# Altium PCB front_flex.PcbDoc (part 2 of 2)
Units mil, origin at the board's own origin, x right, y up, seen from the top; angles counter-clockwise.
Board outline 5591.04 x 1020.3 mil, 4 copper layers (Layer 1 (Top Layer), Layer 2 (PWR), Layer 3 (GND), Layer 4 (Bottom Layer)), stack 21.036 mil thick; 26 components, 44 nets, 150 pads, 87 vias.
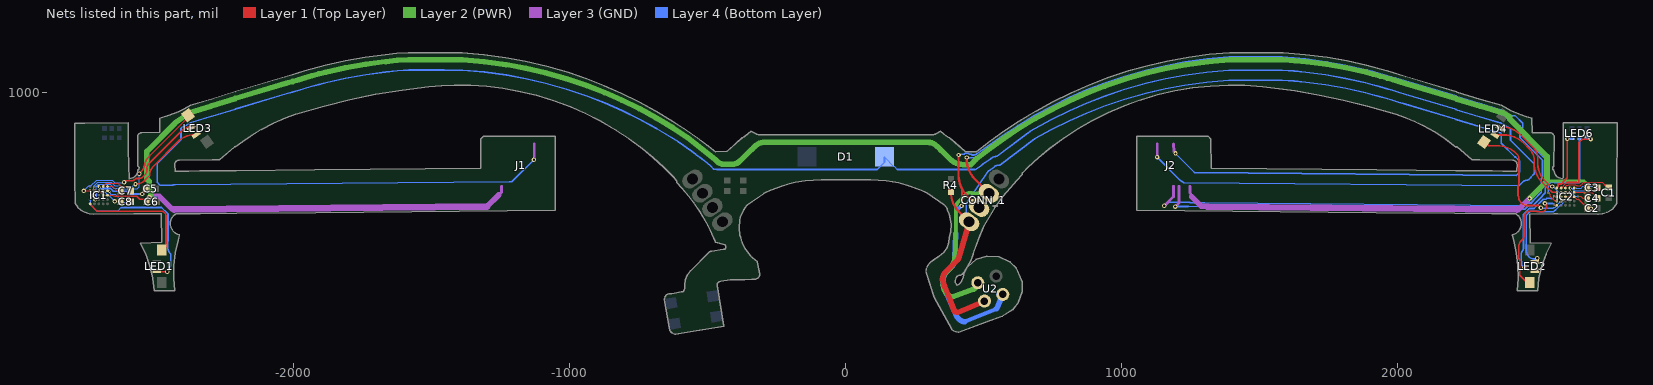
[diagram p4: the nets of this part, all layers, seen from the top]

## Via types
v1: diameter 16, hole 8, Layer 1 (Top Layer) to Layer 4 (Bottom Layer), tented both sides, 43 vias
v2: diameter 8, hole 4, Layer 1 (Top Layer) to Layer 4 (Bottom Layer), tented both sides, 19 vias
v3: diameter 16, hole 8, Layer 3 (GND) to Layer 4 (Bottom Layer), tented both sides, 17 vias
v4: diameter 24, hole 12, Layer 1 (Top Layer) to Layer 4 (Bottom Layer), tented both sides, 3 vias
v5: diameter 20, hole 10, Layer 1 (Top Layer) to Layer 4 (Bottom Layer), tented both sides, 2 vias
v6: diameter 18, hole 8, Layer 1 (Top Layer) to Layer 4 (Bottom Layer), tented both sides, 1 vias
v7: diameter 12, hole 6, Layer 1 (Top Layer) to Layer 4 (Bottom Layer), tented both sides, 1 vias
v8: diameter 24, hole 12, Layer 3 (GND) to Layer 4 (Bottom Layer), tented both sides, 1 vias

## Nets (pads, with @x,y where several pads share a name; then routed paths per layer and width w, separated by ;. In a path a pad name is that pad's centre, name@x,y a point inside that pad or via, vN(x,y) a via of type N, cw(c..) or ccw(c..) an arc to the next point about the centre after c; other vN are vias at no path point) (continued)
LED_LEFT_SIDE_G: IC1.C2 LED1.3 | length 593.7
  Layer 1 (Top Layer) w6: LED1.3@-2493.64,351.14 -2493.49,351.29 v1(-2458.5,351.29)
  Layer 4 (Bottom Layer) w4: v2(-2725.33,626.06) -2727.3,626.06 -2736.83,616.52 -2736.83,594.35 -2715.78,573.3 -2637.09,573.3 -2626.09,584.3
  Layer 4 (Bottom Layer) w6: -2626.09,584.3 -2479.49,584.3 -2461.09,565.89 -2461.09,565.68 -2456.36,560.95 -2456.36,462.57 ; v1(-2458.5,351.29) -2458.2,351.29 -2450.65,358.84 -2450.65,364.12 ccw(c-2452.71,364.12) -2451.26,365.58 ; -2456.99,462.48 -2456.99,440.91 ccw(c-2420.89,440.91) -2446.42,415.39 -2446.42,372.26 -2452.09,366.59
LED_LEFT_SIDE_R: IC1.E1 LED1.1 | length 426.4
  Layer 1 (Top Layer) w4: LED1.1@-2475.93,425.94 LED1.1@-2463.79,438.07
  Layer 1 (Top Layer) w6: IC1.E1@-2738.33,597.3 -2738.33,595.33 -2713.3,570.3 -2479.69,570.3 cw(c-2479.69,553.94) -2468.12,565.51 cw(c-2480.28,553.35) -2463.09,553.35 LED1.1@-2463.09,441.49
LED_LEFT_TOP_B: IC1.B1 LED3.4 | length 530.4
  Layer 1 (Top Layer) w4: v1@-2759.84,644.55 IC1.B1@-2738.33,644.56
  Layer 1 (Top Layer) w6: v1(-2761.09,644.3) -2760.09,644.3 v1@-2759.84,644.55 ; v1@-2615.3,674.53 -2615.53,674.3 -2615.99,674.3 -2608.69,681.59 -2583.23,681.59 -2580.82,684 -2578.86,684 -2573.56,689.3 -2561.12,689.3 ccw(c-2561.12,708.24) -2547.73,694.84 -2539.43,703.15 ccw(c-2556.66,720.38) -2532.29,720.38 -2532.29,723.78 ; -2532.84,723.78 cw(c-2502.72,723.78) -2524.02,745.08 -2406.68,862.42 cw(c-2369.72,825.46) LED3.4@-2369.72,877.73
  Layer 4 (Bottom Layer) w4: v1(-2761.09,644.3) -2742.92,662.47 -2735.95,662.47 -2714.86,683.56 -2659.01,683.56 -2649.75,674.3 v1@-2615.3,674.3
  other v1: -2615.3,675.83
LED_LEFT_TOP_G: IC1.B2 LED3.3 | length 466.4
  Layer 1 (Top Layer) w6: v1(-2574,669) ccw(c-2574,716.7) -2540.27,682.97 -2522.84,700.4 cw(c-2475.06,700.4) -2508.87,734.16 -2420.33,822.71 cw(c-2358.95,761.34) LED3.3@-2358.95,848.13
  Layer 4 (Bottom Layer) w4: v2(-2725.33,647.3) -2725.33,661.78 -2711.55,675.56 -2662.33,675.56 -2649.56,662.8 -2629.36,662.8 -2627.1,660.53 -2585.07,660.53 v1@-2580.3,665.3
LED_LEFT_TOP_R: IC1.D2 LED3.1 | length 567
  Layer 1 (Top Layer) w4: v1@-2563.05,703.59 v1(-2560.3,706.3)
  Layer 1 (Top Layer) w6: v1(-2560.3,706.3) -2554.28,712.37 ccw(c-2586.69,744.77) -2540.85,744.77 cw(c-2462.6,710.62) -2522.98,770.99 -2370.61,923.36 cw(c-2367.89,920.64) LED3.1@-2367.89,924.48
  Layer 4 (Bottom Layer) w4: v2(-2719.84,610.32) -2714.43,615.73 -2714.43,633.5 -2716.09,635.15 -2716.09,642.4 -2715.33,643.16 -2715.33,651.44 -2716.09,652.2 -2716.09,659.7 -2708.23,667.56 -2665.64,667.56 -2652.88,654.8 -2632.68,654.8 -2630.41,652.53 -2567.2,652.53 -2560,659.73 -2560,702.47 v1@-2560.22,702.69
  Layer 4 (Bottom Layer) w10: v1(-2560.3,706.3) -2560.3,704.62 ccw(c-2538.63,704.62) v1@-2560.22,702.69
LED_RIGHT_FRONT_B: IC2.A1 LED6.3 | length 220.4
  Layer 1 (Top Layer) w6: IC2.A1@2577.14,654.79 2577.12,654.92 2581.7,659.49 2581.7,669.52 2594.86,669.52 2601.11,675.77 2601.11,677.19 2615.48,691.56 v1(2615.48,833.36)
  Layer 4 (Bottom Layer) w6: v1(2615.48,833.36) 2630.56,833.36 ccw(c2630.56,837.33) LED6.3@2633.37,834.52
LED_RIGHT_FRONT_G: IC2.A2 LED6.1 | length 270.4
  Layer 1 (Top Layer) w4: IC2.A2@2592.89,654.79 2611.11,673.04
  Layer 1 (Top Layer) w6: 2611.11,673.04 2612.86,674.79 2648.42,674.79 2649.16,674.05 2656.62,674.05 2656.62,819.59 2669,831.97 v1(2699.81,831.97)
  Layer 4 (Bottom Layer) w4: v1@2695.58,831.97 v1(2699.81,831.97)
LED_RIGHT_FRONT_R: IC2.D1 LED6.2 | length 355.9
  Layer 1 (Top Layer) w4: v2(2547.62,636.31) 2553.49,630.44 2553.49,625.24 2569.92,608.81 2574.16,608.81 cw(c2574.16,606.78) IC2.D1@2575.6,608.21
  Layer 4 (Bottom Layer) w6: v2(2547.62,636.31) 2545.95,637.98 2545.95,666.55 2554.74,675.33 2567.16,675.33 2568.99,673.51 2659.5,673.51 2659.5,807.23 2659.39,807.35 2659.39,830.5 cw(c2660.97,830.5) LED6.2@2659.41,830.76 ; LED6.2@2659.41,836.93 LED6.2@2659.41,830.76 ; LED6.2@2659.85,831.62 ccw(c2660.97,830.5) LED6.2@2659.41,830.76
LED_RIGHT_SIDE_B: IC2.C1 LED2.4 | length 392.7
  Layer 1 (Top Layer) w4: v2(2566.62,626.31) 2566.89,626.04 2573.76,626.04 2576.49,623.31 IC2.C1@2577.12,623.31
  Layer 1 (Top Layer) w6: v1(2458.21,366.86) 2459.8,366.86 2461.94,368.99 2472.36,358.57 2486.47,358.57 LED2.4@2491.47,353.57
  Layer 4 (Bottom Layer) w4: 2560.87,615.57 2565.37,620.06 2565.37,625.06 v2(2566.62,626.31)
  Layer 4 (Bottom Layer) w6: v1(2458.21,366.86) 2449.72,375.36 2449.72,388.19 2449.01,388.9 2449.01,418.26 cw(c2462.07,418.26) 2452.83,427.49 ccw(c2443.69,436.64) 2456.62,436.64 2456.62,559.54 2477.39,580.31 2494.36,580.31 2527.97,613.92 2538.01,613.92 2541.25,617.16 2554.5,617.16 2556.09,615.57 2560.87,615.57
LED_RIGHT_SIDE_G: IC2.C2 LED2.3 | length 361.7
  Layer 4 (Bottom Layer) w4: 2572.87,575.81 2572.87,576.19 2591.48,594.8 2594.29,594.8 2600.15,600.66 2600.15,604.8 ccw(c2590.15,604.8) 2597.22,611.87 2595.76,613.34 ccw(c2592.22,609.8) 2592.22,614.8 2591.77,614.8 2588.37,618.2 2588.37,618.98 v2@2589.95,620.55
  Layer 4 (Bottom Layer) w6: 2466.47,427.84 ccw(c2496.87,427.84) 2466.62,424.86 ; v1@2499.66,397.58 cw(c2496.87,427.84) 2466.62,424.86 ; 2572.87,575.81 2565.41,568.34 2513.45,568.34 2511.49,570.31 2481.54,570.31 2466.62,555.39 2466.62,424.86 ; v2@2589.95,620.55 v2(2590.15,620.55)
  other v1: 2506.47,400.36
LED_RIGHT_SIDE_R: IC2.E1 LED2.1 | length 427.5
  Layer 1 (Top Layer) w4: v1(2534.18,598.92) v1@2536.94,596.16 ; v2(2566.7,595.48) 2569.53,592.64 2576.29,592.64 IC2.E1@2577.12,591.81
  Layer 1 (Top Layer) w6: LED2.1@2473.75,312.23 2473.75,310.26 cw(c2473.75,315.97) 2469.72,311.93 2444.68,336.97 cw(c2448.72,341.01) 2443.01,341.01 2442.62,363.38 2442.62,391.94 ccw(c2431.46,391.94) 2439.57,399.61 2439.35,441.79 cw(c2471.06,441.79) 2448.64,464.22 2453.64,469.22 ccw(c2441.62,481.24) 2458.62,481.24 2458.62,548.93 cw(c2479.42,548.93) 2464.71,563.63 2467.64,566.56 cw(c2476.68,557.52) 2476.68,570.31 2504.76,570.31 2506.73,568.34 2528.2,568.34 2529.48,569.62 2541.93,582.07 2539.7,584.29 2539.7,593.4 v1@2536.94,596.16
  Layer 4 (Bottom Layer) w6: v1@2535.79,598.92 2562.72,598.92 2566.16,595.48 v2(2566.7,595.48)
LED_RIGHT_TOP_B: IC2.B1 LED4.4 | length 338.7
  Layer 1 (Top Layer) w4: IC2.B1@2576.29,639.89 IC2.B1@2577.14,639.04
  Layer 1 (Top Layer) w6: LED4.4@2357.5,847.14 2386.15,847.14 cw(c2386.15,747.14) 2456.86,817.85 2477.78,796.93 cw(c2435.03,754.18) 2495.49,754.18 2495.49,745.3 ccw(c2595.49,745.3) 2524.78,674.59 2544.87,654.49 2545.58,654.49 2560.18,639.89 IC2.B1@2576.29,639.89
LED_RIGHT_TOP_G: IC2.B2 LED4.3 | length 359.6
  Layer 1 (Top Layer) w6: LED4.3@2368.27,876.73 2374.95,876.73 cw(c2374.95,776.73) 2445.67,847.44 2460.74,832.37 2493.26,799.85 cw(c2455.72,762.36) 2508.77,762.36 2508.77,741.71 ccw(c2593.4,741.71) 2533.56,681.87 2547.09,668.34 cw(c2545.8,667.06) 2547.62,667.06 2554.35,660.33 v1(2560.95,660.33)
  Layer 4 (Bottom Layer) w4: v1(2560.95,660.33) 2563.1,660.33 2587.14,636.29 v2(2590.14,636.29) ; v2@2588.37,634.56 v2(2590.14,636.29)
LED_RIGHT_TOP_R: IC2.D2 LED4.1 | length 476.6
  Layer 1 (Top Layer) w4: v2(2590.15,604.8) 2590.15,605.83 2591.88,607.56 IC2.D2@2594.05,607.56
  Layer 1 (Top Layer) w6: LED4.1@2316.58,808.49 2319.26,811.17 2327.37,811.17 2330.09,808.45 2360.44,808.45 cw(c2360.44,708.45) 2431.16,779.17 2432.13,778.2 cw(c2412.97,759.04) 2440.06,759.04 2440.06,672.71 cw(c2428.76,672.71) 2436.75,664.72 ; 2436.8,664.15 2436.75,664.11 2436.75,658.99 2436.75,653.87 2436.75,627.59 ccw(c2443.49,627.59) 2438.72,622.82 ccw(c2467.97,622.82) 2447.29,602.15 2448.83,600.61 ccw(c2471.36,623.14) 2471.36,591.27 2511.15,591.27 2519.09,583.34 v1(2519.67,583.34)
  Layer 4 (Bottom Layer) w4: 2568.12,583.81 2569.79,585.48 2570.84,585.48 v2(2590.15,604.8)
  Layer 4 (Bottom Layer) w6: v1@2512.96,583.4 2515.05,581.31 2563.37,581.31 2565.37,583.31
LH_DIODE_ARRAY: D1.1 J1.14 J2.13 | length 8456.1
  Layer 3 (GND) w10: v3(-1129.82,757.59) -1128.83,758.58 J1.14@-1128.83,814.72 ; v3(1128.78,766.97) v3(1128.78,766.97) J2.13@1128.82,814.72
  Layer 4 (Bottom Layer) w4: D1.1@140.75,767.67 140.75,766.68 173.2,734.23 175.14,734.23 187.76,721.61
  Layer 4 (Bottom Layer) w6: -2297.73,914.37 -2298.01,914.29 -2375.27,891.33 -2393.36,880.85 -2404.52,875.15 -2409.09,870.59 -2409.09,829.5 -2494.88,743.71 -2494.88,675.31 -2489.03,669.46 -2484.87,665.3 -2471.45,665.3 -2470.77,664.61 -2438.9,664.61 -2437.39,666.12 -2429.34,666.12 -1219.46,677.21 -1210.2,677.21 v3(-1129.82,757.59) ; -2296.29,914.47 -2212.03,939.84 -2212.05,941.31 -2027.38,995.99 -2004.16,1002.86 -1981.48,1009.58 -1958.79,1016.3 -1934.04,1023.43 -1909.34,1030.15 -1884.54,1036.49 -1812.46,1052.67 -1739.75,1065.65 -1667.03,1075.33 -1624.87,1079.45 -1582.61,1082.47 -1520.87,1082.42 -1454.76,1082.33 -1388.64,1082.2 -1308.84,1075.29 -1229.5,1064.41 -1158.68,1051.25 -1088.65,1034.93 -1011.52,1013.06 -935.43,987.32 -872.62,962.82 -810.87,935.68 -747.3,904.45 -685.15,870.5 -624.51,833.9 -606.54,822.34 -557.94,787.64 -543.31,777.18 ; -542.1,775.97 -528.83,765.98 -502.71,746.45 -487.99,733.43 -479.05,723.73 -466.57,721.83 113.94,721.83 140.75,748.63 D1.1@140.75,766.68 ; 187.76,721.61 468.24,721.61 488.1,734.15 498.32,742.03 521.39,756.89 523.73,759.23 cw(c548.44,734.53) 548.44,769.46 632.61,833.1 654.16,849.06 661.7,854.66 667.81,859.74 684.89,869.72 747.04,903.68 810.61,934.91 872.36,962.04 935.17,986.55 1011.26,1012.28 1088.39,1034.16 1158.42,1050.47 1229.24,1063.63 1308.58,1074.51 1388.38,1081.42 1454.5,1081.56 1520.61,1081.64 1582.35,1081.69 1624.61,1078.67 1666.77,1074.56 1739.49,1064.88 1812.2,1051.89 1884.28,1035.71 1909.08,1029.37 1933.78,1022.66 1958.53,1015.53 1981.22,1008.81 2003.91,1002.08 2027.12,995.21 2211.79,940.53 2211.77,939.06 2296.03,913.69 ; v3(1128.78,766.97) 1128.78,766.06 1212.6,682.24 1225.25,673.65 2434.59,662.56 ; 2296.26,913.39 2296.55,913.3 2373.8,890.34 ; 2375.8,889.34 2393.89,878.86 2405.06,873.16 2409.62,868.6 2409.62,827.52 2495.38,741.76 2495.38,706.16 2484.04,694.83 cw(c2478.31,696.59) 2482.52,692.32 2477.58,687.37 cw(c2465.39,699.59) 2465.39,682.33 ccw(c2465.39,668.63) 2455.7,678.32 2443.72,666.34 cw(c2434.59,675.48) 2434.85,662.56 ; 2434.59,662.56 ccw(c2434.59,675.48) 2434.85,662.56 ; 2434.59,662.56 2434.85,662.56
NetC3_1: C3.1 IC2.A5 | length 84.6
  Layer 1 (Top Layer) w4: v2@2713.51,660.9 2720.15,660.9 C3.1@2724.88,656.17
  Layer 4 (Bottom Layer) w4: v2(2644.86,654.52) 2665.68,654.52 2672.05,660.9 v2(2710.51,660.9) v2@2713.51,660.9
NetC3_2: C3.2 IC2.A4 | length 95.2
  Layer 1 (Top Layer) w4: C3.2@2687.08,656.17 2694.83,648.42 v2(2700.37,648.42)
  Layer 4 (Bottom Layer) w4: v2(2627.13,653.79) 2630.54,653.79 2639.87,644.46 2680.77,644.46 2684.73,648.42 v2(2700.37,648.42)
NetC4_1: C4.1 IC2.B5 | length 93
  Layer 1 (Top Layer) w4: IC2.B5@2640.13,639.04 2673.06,639.06 2673.76,638.35 2705.69,638.35 C4.1@2724.88,619.17
NetC4_2: C4.2 IC2.B4 | length 70.9
  Layer 1 (Top Layer) w4: v2(2653.62,624.31) 2664.72,624.31 2670.72,618.31 2686.23,618.31 C4.2@2687.08,619.17
  Layer 4 (Bottom Layer) w4: v2(2627.13,641.79) 2628.14,641.79 2646.62,623.31 2647.62,624.31 v2(2653.62,624.31)
NetC7_1: C7.1 IC1.A5 | length 51.6
  Layer 1 (Top Layer) w4: IC1.A5@-2675.34,660.3 -2660.26,660.3 cw(c-2660.26,651.14) -2653.79,657.63 ; -2653.78,657.62 -2648.03,651.87 ccw(c-2628.98,670.92) C7.1@-2628.98,643.98
NetC7_2: C7.2 IC1.A4 | length 117.5
  Layer 1 (Top Layer) w4: IC1.A4@-2691.09,660.3 -2679.09,672.3 -2642.45,672.3 cw(c-2642.45,662.52) -2635.54,669.43 ccw(c-2614.05,690.92) -2622.7,661.79 -2615.41,661.79 -2615.2,661.58 -2612.05,661.58 -2611.98,661.5 -2601.89,661.5 -2593.5,653.11 C7.2@-2585.22,653.11
NetC8_1: C8.1 IC1.B5 | length 129.7
  Layer 1 (Top Layer) w4: v1(-2598.13,602.5) -2582.19,602.5 -2591.09,611.4 -2587.19,615.3 C8.1@-2582.68,610.79
  Layer 4 (Bottom Layer) w4: v2(-2667.9,641.54) -2667.9,637.11 -2663.09,632.3 -2646.89,632.3 -2616.15,601.56 -2615.2,602.5 v1(-2598.13,602.5)
NetC8_2: C8.2 IC1.B4 | length 76.9
  Layer 1 (Top Layer) w4: v1(-2649.09,606.3) C8.2@-2628.98,606.3
  Layer 4 (Bottom Layer) w4: v2(-2688.34,641.81) -2688.34,641.55 -2687.32,640.53 -2687.32,642.39 -2676.23,631.3 -2674.09,631.3 v1(-2649.09,606.3)
TP_NOSE: CONN_1.3 J2.8 U2.4 | length 4657.5
  Layer 1 (Top Layer) w8: v1(438.59,765.51) 438.59,757.95 ccw(c538.59,757.95) 467.88,687.24 CONN_1.3@519.31,635.82
  Layer 3 (GND) w10: v3(1154.84,590.24) 1154.84,590.45 1187.87,623.48 J2.8@1187.87,661.18
  Layer 2 (PWR) w13: 398.06,486.21 398.75,486.9 398.75,582.64 cw(c427.55,582.64) 407.18,603 434.04,629.86 cw(c454.43,609.51) 454.43,638.31 ccw(c460.46,644.35) 460.46,635.82 CONN_1.3@519.31,635.82 ; 399.16,521.14 399.44,520.86
  Layer 2 (PWR) w16: 395.49,402.02 398.06,486.21
  Layer 2 (PWR) w20: 395.49,402.02 cw(c346.5,402.19) 381.14,367.54 363.16,349.56 ccw(c387.96,324.77) 352.89,324.77 352.89,307.79 ccw(c408.12,307.79) 369.07,268.74 372.13,265.67 ccw(c386.16,279.71) 386.16,259.86 463.83,288.51 465.89,289.27 468.53,291.91 U2.4@478.7,311.45
  Layer 4 (Bottom Layer) w6: 446.72,762.29 441.53,762.29 cw(c445.6,758.23) 445.6,763.97 465.14,763.97 ccw(c465.14,789.22) 482.99,771.37 612.57,861.42 618,864.93 619.5,865.93 624.25,869.12 684.89,905.72 747.04,939.68 810.61,970.91 872.36,998.04 935.17,1022.55 1011.26,1048.28 1088.39,1070.16 1158.42,1086.47 1229.24,1099.63 1308.58,1110.51 1388.38,1117.42 1454.5,1117.56 1520.61,1117.64 1582.35,1117.69 1624.61,1114.67 1666.77,1110.56 1739.49,1100.88 1812.2,1087.89 1884.28,1071.71 1909.08,1065.37 1933.78,1058.66 1958.53,1051.53 1981.22,1044.81 2003.91,1038.08 2027.12,1031.21 2211.79,976.53 2211.77,975.06 2296.03,949.69 ; v3(1154.84,590.24) 1167.93,603.33 1246.67,603.33 1248.43,601.56 1300.44,601.56 2455.35,591.12 2460.02,591.22 2469.11,600.31 2485.52,600.31 2485.92,600.7 2485.92,603.32 2493.6,611.01 2493.6,611.41 2521.28,639.08 2521.28,689.1 2525.38,693.2 2525.38,755.7 2443.62,837.45 2443.62,879.45 2419.72,903.35 2416.68,903.35 2415.09,904.93 2414.25,904.93 2412.08,907.1 ; 2292.89,951.26 2370.14,928.3 ; 2372.14,927.3 2390.24,916.83 2408.88,907.31 ; 2409.08,907.35 2411.75,906.27
TP_NOSE_GND: CONN_1.2 J2.6 U2.2 | length 4836.5
  Layer 1 (Top Layer) w8: v1(409.35,774.53) 409.35,699.47 ccw(c509.35,699.47) 421.27,652.12 ; v1(420,590) ccw(c416.94,593.06) 421.27,593.06 421.27,652.12 ; CONN_1.2@483.18,584.21 438.64,628.76 cw(c509.35,699.47) 421.27,652.12
  Layer 3 (GND) w10: v3(1194.58,587.58) 1207.56,600.56 J2.6@1207.56,661.18
  Layer 4 (Bottom Layer) w6: 418.26,777.29 429.16,777.29 432.38,780.51 444.81,780.51 448.02,777.29 454.93,777.29 457.6,774.61 466.22,774.61 ccw(c466.22,787.61) 475.41,778.42 571.2,846.08 624.25,881.12 684.89,917.72 747.04,951.68 810.61,982.91 872.36,1010.04 935.17,1034.55 1011.26,1060.28 1088.39,1082.16 1158.42,1098.47 1229.24,1111.63 1308.58,1122.51 1388.38,1129.42 1454.5,1129.56 1520.61,1129.64 1582.35,1129.69 1624.61,1126.67 1666.77,1122.56 1739.49,1112.88 1812.2,1099.89 1884.28,1083.71 1909.08,1077.37 1933.78,1070.66 1958.53,1063.53 1981.22,1056.81 2003.91,1050.08 2027.12,1043.21 2211.79,988.53 2211.77,987.06 2296.03,961.69 ; v3(1194.58,587.58) 1240.84,587.58 1242.54,589.28 2435.87,578.34 2461.28,578.34 2473.25,590.31 2489.66,590.31 2524.71,625.36 2524.71,627.08 2534.87,637.24 2534.87,689.09 2535.38,689.59 2535.38,759.84 2453.62,841.59 2453.62,889.31 2425.62,917.31 2412.57,917.31 2412.53,917.35 2393.89,926.86 2375.8,937.34 ; 2296.26,961.39 2296.55,961.3 2373.8,938.34
  Layer 4 (Bottom Layer) w13: 398.75,489.01 398.75,568.75 v1(420,590)
  Layer 4 (Bottom Layer) w16: 431.66,170.53 545.7,216.65
  Layer 4 (Bottom Layer) w20: 398.75,489.01 396.08,401.59 cw(c345.83,401.59) 381.36,366.06 363.38,348.08 ccw(c388.18,323.29) 353.11,323.29 353.11,306.31 366.44,270.48 366.51,270.31 403.71,186.62 404.49,185.84 411.41,178.92 ccw(c431.66,199.16) 431.66,170.53 ; 545.7,216.65 547.37,218.33 547.83,219.38 U2.2@569.33,269.18 U2.2@554.75,269.18
TP_THERMISTOR: CONN_1.1 J2.7 R4.1 U2.3 | length 4268.7
  Layer 1 (Top Layer) w6: R4.1@381.34,639.75 R4.1@381.34,641.08 ; CONN_1.1@447.05,532.61 CONN_1.1@448.32,530.19
  Layer 1 (Top Layer) w8: R4.1@381.34,639.75 ccw(c481.34,639.75) 410.62,569.04 CONN_1.1@447.05,532.61
  Layer 1 (Top Layer) w20: 358.92,295.6 cw(c391.84,295.6) 358.95,296.92 ; CONN_1.1@448.32,530.19 409.86,400.79 cw(c409.36,400.79) 409.82,400.6 cw(c392.05,407.98) 405.66,394.38 377.32,366.04 362.92,351.63 ccw(c392.21,322.34) 350.8,323.4 ccw(c356.79,323.24) 351.08,321.41 358.95,296.92 ; U2.3@500.06,244.05 406.65,204 401.77,204 396.6,206.16 393.16,209.61 359.39,295.78 358.95,296.92
  Layer 3 (GND) w10: J2.7@1187.87,814.72 1189.49,785.87
  Layer 4 (Bottom Layer) w6: CONN_1.1@436.54,520.22 436.54,600.66 ; 436.59,599.27 516.87,716.21 537.57,730.57 cw(c555.12,713.02) 555.12,737.84 558.28,737.84 684.89,833.72 747.04,867.68 810.61,898.91 872.36,926.04 935.17,950.55 1011.26,976.28 1088.39,998.16 1158.42,1014.47 1229.24,1027.63 1308.58,1038.51 1388.38,1045.42 1454.5,1045.56 1520.61,1045.64 1582.35,1045.69 1624.61,1042.67 1666.77,1038.56 1739.49,1028.88 1812.2,1015.89 1884.28,999.71 1909.08,993.37 1933.78,986.66 1958.53,979.53 1981.22,972.81 2003.91,966.08 2027.12,959.21 2211.79,904.53 2211.77,903.06 2296.03,877.69 ; v3(1195.18,780.18) 1264.42,710.94 2430.56,700.25 2443.4,713.09 2443.4,751.31 2427.4,767.31 2425.92,767.31 2375.8,817.43 2375.8,851.85 ; 2296.26,877.39 2296.55,877.3 2373.8,854.34
VBAT: C2.2 C6.2 IC1.B3 IC1.C4 IC1.C5 IC2.B3 IC2.C3 IC2.C4 IC2.C5 J1.1 J2.2 | length 9040
  Layer 1 (Top Layer) w4: IC1.B3@-2707.32,644.38 -2691.57,628.63 -2691.09,628.8 -2659.85,628.8 ; IC2.B3@2608.64,639.04 2608.64,623.31 2624.38,623.31 IC2.C5@2640.12,623.31 ; IC2.C5@2640.17,623.31 2650.17,613.31 2657.32,613.31
  Layer 1 (Top Layer) w6: -2659.85,628.8 -2648.1,624.55 -2583.49,624.44 -2569.37,624.93 -2558.55,614.11 -2545.99,614.11 -2537.99,606.11 C6.2@-2537.99,605.73 ; C6.2@-2537.99,605.3 C6.2@-2537.99,605.73 ; v5@-2524.56,619.15 C6.2@-2537.99,605.73 ; IC2.C5@2640.12,623.31 IC2.C5@2640.17,623.31 ; 2657.32,613.31 C2.2@2687.08,583.55 ; C2.2@2687.08,583.17 C2.2@2696.76,583.17
  Layer 3 (GND) w10: -1257.1,630.31 -1247.85,639.56 -1247.85,660.28 J1.1@-1246.94,661.18 ; J2.2@1246.93,661.18 1247.83,660.28 1247.83,636.65 1250.99,633.5 1250.99,626.13 1253.51,623.61
  Layer 3 (GND) w20: v5@-2519.9,625.74 -2488.41,625.74 -2439.68,577.01 -2433.96,577.01 -2428.24,577.01 ; -1299.82,588.01 -1299.4,588.01 -1257.1,630.31 ; 1253.51,623.61 1287.79,589.33 1310.85,589.33 ; 2432.1,575.88 2437.27,575.88 v1(2478.6,617.22)
  Layer 3 (GND) w25: -2433.96,577.01 -1299.82,588.01 ; 1310.85,587.06 2432.85,576.77
  Layer 2 (PWR) w10: 2541.72,680.34 2676.45,680.34 2682.31,674.48 2682.31,602.02 2701.62,582.71 v1(2701.62,580.31)
  Layer 2 (PWR) w20: v5@-2518.26,625.46 -2518.26,640.07 -2524.79,646.6 -2524.79,679.43 -2532.63,687.27 -2532.63,787.84 -2429.75,890.72 -2378.1,927.91 -2300.85,950.87 -2300.56,950.96 ; -2296.81,952.41 -2212.55,977.78 -2212.57,979.25 -2027.9,1033.93 -2004.69,1040.81 -1982,1047.53 -1959.31,1054.25 -1934.56,1061.38 -1909.86,1068.09 -1885.06,1074.44 -1812.98,1090.62 -1740.27,1103.6 -1667.55,1113.28 -1625.39,1117.39 -1583.13,1120.41 -1521.39,1120.37 -1455.28,1120.28 -1389.16,1120.15 -1309.36,1113.24 -1230.02,1102.35 -1159.2,1089.19 -1089.17,1072.88 -1012.04,1051 -935.95,1025.27 -873.14,1000.76 -811.39,973.63 -747.82,942.4 -685.67,908.44 -625.03,871.84 -571.98,836.8 -471.95,757.41 -464.6,750.07 ccw(c-441.83,772.85) -441.83,740.64 -413.34,740.75 ccw(c-413.34,784.25) -382.61,753.46 ; -382.58,753.49 -342.82,793.25 -341.75,793.25 -330.34,804.66 cw(c-292.51,766.84) -292.51,820.33 297.84,820.33 cw(c297.84,774.62) 330.16,806.94 344.64,792.46 345.71,792.46 378.72,759.45 ; 378.74,759.43 ccw(c425.78,806.5) 425.78,739.96 453.34,739.96 466.23,752.85 466.23,753.82 472.35,759.95 473.08,759.95 523.26,798.97 574.87,836.01 627.92,871.05 688.56,907.65 750.71,941.61 814.28,972.84 876.03,999.97 938.84,1024.48 1014.93,1050.21 1092.06,1072.09 1162.09,1088.4 1232.91,1101.56 1312.25,1112.45 1392.05,1119.36 1458.17,1119.49 1524.28,1119.57 1586.02,1119.62 1628.28,1116.6 1670.44,1112.49 1743.16,1102.81 1815.87,1089.82 1887.95,1073.65 1912.75,1067.3 1937.45,1060.59 1962.2,1053.46 1984.89,1046.74 2007.58,1040.02 2030.79,1033.14 2215.46,978.46 2215.44,976.99 2299.7,951.62 ; 2302.15,951.04 2302.44,950.95 2379.69,927.99 2397.78,917.51 2407.1,912.76 2407.1,903.97 2541.72,769.35 2541.72,680.34 v1(2478.6,617.22)
  other v5: -2524.53,618.86
VOUT_L_LED: C5.2 IC1.A3 | length 189.3
  Layer 1 (Top Layer) w6: v1(-2549.13,633.17) -2549.13,633.29 -2541.9,640.51 cw(c-2526.46,640.51) C5.2@-2537.38,651.43
  Layer 4 (Bottom Layer) w4: v2(-2704.09,657.56) -2697.83,651.3
  Layer 4 (Bottom Layer) w6: -2697.83,651.3 -2694.41,651.3 -2692.9,652.81 -2663.62,652.81 -2654.34,643.53 -2605.73,643.53 -2594.8,632.6 -2594.23,633.17 v1(-2549.13,633.17)
VOUT_R_LED: C1.2 IC2.A3 | length 175.2
  Layer 1 (Top Layer) w4: IC2.A3@2608.62,654.55 IC2.A3@2608.87,654.81 ; IC2.A3@2608.64,654.79 2609.8,654.81 2611.97,656.98 2611.97,662.59 2613.42,664.04 2618.08,664.04 2619.83,665.79 2644.69,665.79 2645.96,664.52 2649,664.52 2650.21,663.31 2662.42,663.31 2664.15,665.04 2664.66,665.04 2666.03,666.41 2668.75,669.13 2670.11,670.49 2670.11,670.6 2675.04,675.53 2741.52,675.53 2751.17,665.87 2751.17,665.06 2760.17,656.06 C1.2@2760.98,656.06
pads on no net: IC1.D3 IC1.E2 IC2.D3 IC2.E2 J1.3 J2.1 J2.4 J2.5

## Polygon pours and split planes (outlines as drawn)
GND on Layer 3 (GND) "GND-No Net 1" (hatched 45Degree grid 19.68 track 9.84, remove dead copper, pour order 18): 579 vertices, not listed, extent -2833.81,33.5 2833.84,1149.04
GND on Layer 3 (GND) "GND-No Net 2" (hatched 45Degree grid 20 track 8, remove dead copper, pour order 17): 2429.09,707.09 2429.09,570.77 1070.97,584.2 1070.97,828.17 1311.43,828.17 1311.43,717.33
GND on Layer 3 (GND) "GND-No Net 3" (hatched 45Degree grid 20 track 8, remove dead copper, pour order 15): -2428.88,707.11 -2428.88,570.78 -1070.76,584.21 -1070.76,828.18 -1311.21,828.19 -1311.21,717.34

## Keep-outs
Keep-Out Layer:
  lines w2: 556.62,769.02 cw(c556.62,764) 559.33,768.23 ; 617.63,675.94 617.67,675.98 617.63,675.94 ; 617.63,675.94 617.59,675.89 617.63,675.94 ; 636.74,696.82 636.76,696.84 636.74,696.82
  lines w3.94: -2428.76,715.67 -2424.82,715.71 -2380.81,716.14 -2341.51,716.5 -2209.43,717.72 -1923.84,720.31 -1323.01,726.93 -1322.62,728.31 -1322.62,832.13 -1311.87,842.87 -1053.37,843.15 -1053.37,573.35 -1920.92,565.39 -2206.48,562.76 -2340.1,561.53 -2379.43,561.18 -2423.37,560.78 -2427.3,560.75 ; -2428.76,715.67 -2428.76,715.67 ; -2428.76,715.67 -2430.53,716.1 -2431.87,739.96 -2431.51,743.23 -2430.45,746.61 -2428.6,749.65 -2426.16,752.16 -2423.17,754.09 -2419.86,755.28 -2416.24,755.67 -2296.4,756.81 -2269,757.05 -2214.66,803.62 -2213.05,804.25 -2211.91,803.98 -2185.96,822.4 -2157.7,842.48 -2118.8,866.61 -2074.59,889.65 -2028.48,909.25 -1993.48,921.42 -1889.86,951.57 -1797.22,974.49 -1703.72,993.82 -1607.5,1009.72 -1510.77,1021.69 -1464.86,1025.47 -1418.8,1027.24 -1359.78,1026.69 -1300.88,1022.83 -1242.38,1015.79 -1178.37,1004.25 -1121,990.39 -1058.29,971.38 -997.14,948.62 -943.25,924.92 -890.45,898.15 -833.8,865.12 -784.27,832.28 -736.79,796.85 -697.42,764.25 -659.59,729.8 -623.44,693.58 -611.96,680.4 -612.23,674.7 -594.48,654.35 -569.95,626.2 -551.37,602.58 -529.04,570.45 -499.12,518.64 -485.26,489.11 -473.45,460.33 -473.3,459.87 -473.05,459.46 -472.71,459.1 -472.31,458.84 -437.27,448.64 -435.85,446.56 -434.93,444.21 -434.56,441.72 -434.77,439.2 -435.54,436.8 -436.82,434.63 -438.57,432.81 -444.04,432.81 -484.95,425.88 -487.69,425.63 -490.33,424.83 -492.75,423.52 -494.87,421.75 -562.55,354.07 -574.17,338.92 -581.49,321.28 -584,302.34 -584,289.35 -584.27,286.95 -585.06,284.66 -586.35,282.61 -588.06,280.9 -590.1,279.62 -592.39,278.82 -594.79,278.56 -630.97,272.46 -636.21,272.46 -640.82,271.94 -645.19,270.41 -649.12,267.94 -652.4,264.66 -654.87,260.74 -656.4,256.36 -656.92,251.75 -655.54,240.21 -640.14,149.11 -637.66,138.01 -630.22,130.53 -626.33,127.56 -621.81,125.69 -616.96,125.06 -574.71,131.87 -441.25,154.43 -466.09,301.36 -466.09,303.32 -465.77,306.2 -464.81,308.93 -463.28,311.38 -461.23,313.42 -458.78,314.96 -456.05,315.92 -453.18,316.24 -442.03,318.13 -417.27,322.3 -366.01,323.05 -339.63,323.29 -331.6,323.29 -327.12,323.79 -322.86,325.28 -319.03,327.68 -315.84,330.88 -313.44,334.7 -311.95,338.96 -311.44,343.44 -319.95,387.1 -338.61,402.73 -344.48,408.36 -357.27,424.51 -365.22,437.69 -370.66,447.46 -374.16,456.24 -377.62,465.53 -380.66,475.69 -383.33,484.55 -384.63,493.44 -385.74,500.96 -385.93,511.08 -385.93,519.7 -384.63,528.48 -383.18,537.97 -381.56,548.64 -381.56,550.11 -379.11,557.79 -369.86,575.98 -357.54,592.91 -355.77,594.29 -296.32,635.16 -288.6,638.98 -272.77,646.26 -226.63,663.66 -204.74,670 -182.46,675.27 -146.04,681.38 -88.84,685 89.82,685 146.95,681.42 169.94,677.91 192.46,673.31 227.58,663.74 273.8,646.34 289.71,638.98 297.15,635.35 356.95,594.29 358.09,593.5 367.72,580.97 367.69,578.1 367.8,577.01 368.16,575.98 375.48,560.35 383.2,523.85 381.27,495.74 375.68,476.37 375.48,475.51 373.48,456.92 367.89,439.91 355.6,421.53 337.69,407.59 319.11,394.32 306.7,385.43 306.07,384.91 305.84,384.68 297.82,374.23 292.78,362.07 291.07,349.01 291.31,347.43 320.44,258.06 320.84,257.16 384.03,143.1 384.89,141.96 391.74,136.7 399.72,133.4 408.28,132.28 410.01,132.59 521.51,173.62 567.33,190.31 568.24,190.7 604.93,212.99 605.4,213.62 605.48,213.73 605.52,213.73 624.85,238.34 625.64,239.76 639.58,279.21 639.85,280.82 640.21,312.55 640.12,313.6 639.81,314.6 618.99,362.95 618.56,363.77 617.96,364.48 595.8,387.16 594.3,388.22 556.23,405.94 555.32,406.29 554.34,406.41 512.37,408.22 511.52,408.22 510.68,408.02 474.5,397.08 473.54,396.68 472.69,396.1 442.77,370.7 441.59,369.28 428.32,345.27 427.85,344.09 427.69,342.83 426.03,330.3 421.2,318.62 413.52,308.58 410.44,306.09 406.93,304.28 403.12,303.22 399.89,307.45 397.85,312.36 397.14,317.63 397.99,323.99 400.45,329.93 404.34,335.03 406.57,336.74 409.16,337.82 411.94,338.18 415.56,338.57 419.01,339.74 422.12,341.62 424.76,344.13 426.78,347.16 454.5,393.34 455.01,394.48 461.51,415.86 481.59,471.25 498.99,510.98 508.52,529.17 541.03,584.56 569.5,623.5 597.37,655.51 620.21,681.69 639.3,702.55 640.03,703.57 640.48,704.74 640.64,705.98 640.64,709.61 660.69,729.68 698.48,764.17 737.86,796.81 788.49,834.41 841.4,869.13 892.66,898.7 951.08,928.07 1010.89,953.66 1066.36,973.7 1129.04,992.28 1192.23,1006.89 1256.67,1017.68 1321.67,1024.49 1387.03,1027.36 1446.16,1026.5 1511.75,1021.73 1570.18,1015 1628.37,1006.81 1715.77,991.77 1803.72,973.31 1890.81,951.65 1994.43,921.46 2029.47,909.33 2061.87,895.98 2093.37,880.98 2133.37,858.66 2174.86,831.34 2211.87,802.6 2214.19,804.25 2215.34,803.98 2270.18,757.05 2297.58,756.81 2417.19,755.71 2420.41,755.39 2423.8,754.33 2426.87,752.52 2429.43,750.08 2431.36,747.13 2432.58,743.82 2433.01,740.24 2432.82,718.19 2432.38,716.77 2432.36,715.74 2430.3,715.75 2382.03,716.14 2342.7,716.5 2210.57,717.72 1925.02,720.31 1326.04,725.79 1324.63,726.22 1323.52,831.85 1312.78,842.87 1054.31,842.87 1054.31,573.35 1922.11,565.39 2207.66,562.76 2341.28,561.53 2380.53,561.18 2429.51,560.75 2437.3,554.72 2442.7,547.56 2446.48,539.41 2448.41,530.63 2448.45,521.65 2446.6,512.87 2442.89,504.68 2437.54,497.48 2430.81,491.53 2422.93,487.16 2415.65,484.96 2420.89,465.24 2430.61,420.04 2435.93,374.02 2436.75,327.68 2433.21,283.03 2507.89,282.36 2512.42,326.97 2522.58,372.28 2538.21,416.06 2557.89,455.51 2481.6,456.18 2480.22,456.61 2480.02,559.21 2480.45,560.59 2566.64,560.94 2581.24,560.79 2726.44,559.45 2742.74,561.06 2758.33,566.06 2779.74,578.46 2793.96,598.46 2794.71,688.42 2795.1,733.07 2795.18,742.91 2795.53,787.09 2795.61,793.94 2796.64,891.06 2761.4,891.06 2601.48,891.3 2600.65,796.5 2600.57,788.9 2600.22,744.72 2600.14,734.88 2599.74,691.34 2597.46,688.86 2591.36,689.53 2584.55,691.93 2578.45,695.83 2573.41,700.94 2569.63,707.09 2567.3,713.9 2566.71,719.96 2565.65,720.31 2564.43,720.98 2563.37,721.85 2562.54,722.95 2561.91,724.21 2562.3,729.57 2563.09,730.71 2564.12,731.65 2565.26,732.4 2566.6,732.87 2567.66,839.57 2567.34,842.91 2566.32,846.02 2564.67,848.9 2562.38,851.3 2559.67,853.19 2556.6,854.41 2553.29,854.96 2551.99,854.96 2489.63,855.43 2488.25,855.83 2487.19,907.52 2467.93,912.99 2447.89,919.76 2411.12,935.31 2376.36,954.33 2299.19,977.32 2215.34,1002.56 2213.72,1004.09 2029.98,1058.9 2008.37,1065.31 1985.69,1072.01 1961.32,1079.25 1887.15,1099.41 1816.67,1115.27 1745.49,1128.07 1665.73,1138.66 1585.57,1145.35 1391.75,1145.08 1317.26,1138.74 1243.09,1128.98 1164.67,1114.72 1094.39,1098.46 1024.82,1079.02 948.68,1053.82 880.97,1027.76 814.59,998.7 751.24,967.6 689.08,933.66 628.37,897.01 575.41,862.01 523.8,825 473.92,786.18 433.09,786.81 396.83,818.5 376.28,836.85 369.31,839.72 355.14,851.26 344.15,860.35 326.99,850.98 325.69,850.39 321.87,849.09 317.89,848.31 313.88,848.03 -312.54,848.03 -316.4,848.27 -320.37,849.02 -324.31,850.31 -325.65,850.91 -342.93,860.43 -353.92,851.3 -367.5,840.12 -374.82,837.05 -395.65,818.5 -430.33,787.48 -471.12,785.67 -497.89,806.14 -537.77,836.14 -579,865.27 -584.19,868.82 -627.14,896.97 -687.85,933.62 -750.02,967.56 -813.33,998.66 -875.22,1025.87 -938.25,1050.43 -1006.63,1073.74 -1083.6,1095.94 -1160.96,1114.17 -1231.67,1127.28 -1310.92,1138.15 -1390.53,1145.04 -1584.39,1145.31 -1626.44,1142.32 -1668.4,1138.23 -1741.04,1128.58 -1813.88,1115.59 -1886,1099.41 -1960.22,1079.21 -1982.89,1072.52 -2005.57,1065.79 -2028.8,1058.9 -2212.42,1004.53 -2297.7,977.4 -2374.98,954.41 -2396.32,942.24 -2418.6,931.26 -2452.22,917.79 -2485.88,907.68 -2485.96,857.91 -2486.4,856.53 -2550.81,854.96 -2551.95,854.96 -2555.26,854.45 -2558.33,853.27 -2561.08,851.42 -2563.37,849.05 -2565.06,846.22 -2566.12,843.11 -2566.51,839.68 -2565.53,732.91 -2563.37,731.97 -2562.3,731.1 -2561.44,730.04 -2560.81,728.82 -2561.87,722.24 -2564,720.55 -2565.29,720.04 -2566.04,714.41 -2568.21,707.6 -2571.87,701.38 -2576.83,696.18 -2582.85,692.2 -2589.63,689.68 -2595.77,688.86 -2597.3,689.17 -2598.96,734.88 -2599.03,744.72 -2599.43,788.9 -2599.47,796.5 -2600.29,891.3 -2758.09,889.96 -2794.4,889.96 -2794.39,787.13 -2794,742.95 -2793.92,733.11 -2793.52,688.42 -2792.77,598.46 -2783.56,585.43 -2771.48,574.41 -2757.34,566.14 -2741.79,561.1 -2725.37,559.49 -2580.06,560.79 -2565.45,560.94 -2481.4,561.69 -2479.98,561.3 -2477.93,458.74 -2556.75,455.51 -2537.14,416.34 -2521.51,372.6 -2511.28,327.28 -2506.75,282.36 -2432.03,283.03 -2435.57,327.4 -2434.78,373.74 -2429.47,419.76 -2419.74,465.12 -2414.47,484.96 -2421.28,486.97 -2429.15,491.22 -2436,497.05 -2441.44,504.21 -2445.26,512.36 -2447.22,521.1 -2447.3,530.08 -2445.45,538.9 -2441.83,547.09 -2436.51,554.33 -2429.98,560.12 -2427.3,560.75 ; -2427.3,560.75 -2427.3,560.75
  lines w7.87: -2781.31,852.91 -2781.07,847.49 -2779.84,842.2 -2777.66,837.23 -2774.61,832.74 -2770.79,828.89 -2766.33,825.8 -2761.39,823.57 -2756.11,822.29 -2750.7,822 -2747.8,822.25 -2744.94,822.79 -2739.8,824.54 -2735.07,827.19 -2730.91,830.67 -2727.45,834.85 -2724.81,839.59 -2723.09,844.73 -2722.33,850.11 -2722.58,855.53 -2723.81,860.81 -2725.98,865.78 -2729.03,870.27 -2732.85,874.13 -2737.31,877.22 -2742.26,879.44 -2747.53,880.72 -2752.95,881.01 -2755.84,880.76 -2758.7,880.22 -2763.84,878.48 -2768.57,875.82 -2772.74,872.35 -2776.2,868.17 -2778.83,863.43 -2780.56,858.28 -2781.31,852.91 ; 2722.35,850.49 2723.03,845.11 2724.69,839.94 2727.26,835.17 2730.66,830.94 2734.78,827.41 2739.48,824.7 2742.18,823.61 2744.97,822.79 2750.34,822.02 2755.76,822.24 2761.05,823.45 2766.03,825.61 2770.53,828.64 2774.39,832.45 2777.5,836.89 2779.74,841.84 2781.04,847.1 2781.35,852.52 2780.67,857.9 2779.02,863.07 2776.44,867.85 2773.04,872.07 2768.92,875.6 2764.22,878.32 2761.52,879.41 2758.73,880.22 2753.36,881 2747.94,880.77 2742.65,879.56 2737.67,877.41 2733.18,874.37 2729.31,870.57 2726.2,866.12 2723.96,861.18 2722.66,855.91 2722.35,850.49

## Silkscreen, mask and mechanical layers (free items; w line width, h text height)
Top Overlay:
  rectangle: -32.75,735.75 64.68,757.04
  rectangle: -34,786.24 65.03,809.79
  rectangle: -34,685.81 67.21,707.01
  rectangle: -34,685.81 -10.11,809.79
  rectangle: -84.35,830.51 64.68,851.71
  rectangle: -84.35,684.93 -57.97,851.71
  text "FRONT FLEX  v2.1 / 04.08.2020" at -1659.29,1044.6 h23.62
  text "PATRICK CHWALEK & DAVID RAMSAY" at 989.07,1033.76 h33.46
Bottom Overlay:
  text "BLINK_CATHODE" at -251.16,791.46 h20 r45
  text "BLINK_SIG" at -350.15,777.31 h20 r45
  text "GND" at -463.29,749.03 h20 r45
  text "GND" at 502,706.98 h20 r305
  text "BLINK_PWM" at -273.72,700.89 h20 r45
  text "TP_NOSE" at 471.08,661.7 h20 r305
  text "TP_NOSE_GND" at 432.82,609.14 h20 r305
  text "TP_THERMISTOR" at 400.95,563.29 h20 r305
Stiffener:
  lines w3.94: -2567.44,559.11 -2481.94,560.37 -2481.02,459.89 ; -1325.7,729.49 -1325.7,569.86 -1052.14,572.1 ; 1052.2,572.03 1325.48,569.53 ; 2480.29,460.31 2481.21,560.79 2566.7,559.53
  lines w4: -2798.16,679.58 -2598.8,681.4 ; -2797.97,679.59 -2797.28,598.67 -2797.1,598.1 -2787.45,584.48 -2775,573.06 -2760.38,564.54 -2744.3,559.33 -2727.48,557.65 -2582.04,558.98 -2567.44,559.11 ; -2598.16,681.41 -2430.23,682.94 -2429.18,559.11 ; -2481.02,459.89 -2559.76,459.17 -2560.47,458.91 -2560.76,457.95 -2539.96,416.39 -2524.45,372.92 -2514.31,327.89 -2509.67,281.91 -2509.49,281.39 -2508.86,281.01 -2430.94,281.72 -2430.36,281.91 -2429.95,282.6 -2433.63,328.8 -2432.82,374.89 -2427.55,420.68 -2417.87,465.77 -2412.2,487.19 -2412.5,487.92 -2421.13,490.56 -2428.54,494.61 -2434.93,500.14 -2440,506.9 -2443.52,514.58 -2445.33,522.83 -2445.35,531.28 -2443.58,539.54 -2440.09,547.24 -2435.05,554.02 -2428.88,559.4 ; -1325.7,729.49 -1325.7,834.02 -1325.4,834.62 -1313.69,846.33 -1313.06,846.55 -1053.02,846.78 -1052.42,846.94 -1051.83,846.74 -1051.43,845.94 -1051.43,572.83 -1051.86,572.18 ; -576.21,134.32 -614.99,127.77 -618.48,127.48 -622.04,127.8 -625.68,128.79 -629.07,130.42 -632.12,132.65 -634.71,135.39 -638.33,139.79 -657.91,252.71 -656.74,255.66 -655.95,259.32 -654.5,262.81 -652.44,265.97 -649.85,268.7 -646.79,270.92 -643.39,272.54 -639.75,273.53 -467.2,302.71 ; 1052,572.03 1051.36,572.46 1051.21,573.03 1051.21,846.26 1051.58,846.78 1052.19,846.99 1053,846.55 1312.95,846.55 1313.55,846.26 1325.44,834.21 1325.53,833.61 1325.48,833.09 1325.48,569.53 ; 2428.15,559.82 2434.31,554.44 2439.36,547.66 2442.84,539.96 2444.62,531.7 2444.6,523.25 2442.79,515 2439.27,507.32 2434.2,500.56 2427.81,495.03 2420.39,490.98 2411.76,488.34 2411.47,487.61 2417.13,466.19 2426.82,421.1 2432.09,375.31 2432.89,329.22 2429.21,283.02 2429.63,282.33 2430.21,282.14 2508.12,281.43 2508.75,281.81 2508.94,282.33 2513.57,328.31 2523.72,373.34 2539.23,416.81 2560.02,458.37 2559.73,459.33 2559.02,459.59 2480.29,460.31 ; 2428.44,559.53 2429.49,683.36 2597.42,681.83 ; 2566.7,559.53 2581.31,559.4 2726.75,558.07 2743.57,559.75 2759.65,564.96 2774.26,573.48 2786.72,584.9 2796.37,598.52 2796.55,599.09 2797.24,680.01 ; 2598.06,681.82 2797.42,680
  lines w4.02: -576.21,134.32 -441.25,154.43 -467.2,302.71
Board Outline:
  lines w2: -2781.31,852.91 -2780.56,858.28 -2778.83,863.43 -2776.2,868.17 -2772.74,872.35 -2768.57,875.82 -2763.84,878.48 -2758.7,880.22 -2755.84,880.76 -2752.95,881.01 -2747.53,880.72 -2742.26,879.44 -2737.31,877.22 -2732.85,874.13 -2729.03,870.27 -2725.98,865.78 -2723.81,860.81 -2722.58,855.53 -2722.33,850.11 -2723.09,844.73 -2724.81,839.59 -2727.45,834.85 -2730.91,830.67 -2735.07,827.19 -2739.8,824.54 -2744.94,822.79 -2747.8,822.25 -2750.7,822 -2756.11,822.29 -2761.39,823.57 -2766.33,825.8 -2770.79,828.89 -2774.61,832.74 -2777.66,837.23 -2779.84,842.2 -2781.07,847.49 -2781.31,852.91 ; 2722.35,850.49 2722.66,855.91 2723.96,861.18 2726.2,866.12 2729.31,870.57 2733.18,874.37 2737.67,877.41 2742.65,879.56 2747.94,880.77 2753.36,881 2758.73,880.22 2761.52,879.41 2764.22,878.32 2768.92,875.6 2773.04,872.07 2776.44,867.85 2779.02,863.07 2780.67,857.9 2781.35,852.52 2781.04,847.1 2779.74,841.84 2777.5,836.89 2774.39,832.45 2770.53,828.64 2766.03,825.61 2761.05,823.45 2755.76,822.24 2750.34,822.02 2744.97,822.79 2742.18,823.61 2739.48,824.7 2734.78,827.41 2730.66,830.94 2727.26,835.17 2724.69,839.94 2723.03,845.11 2722.35,850.49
